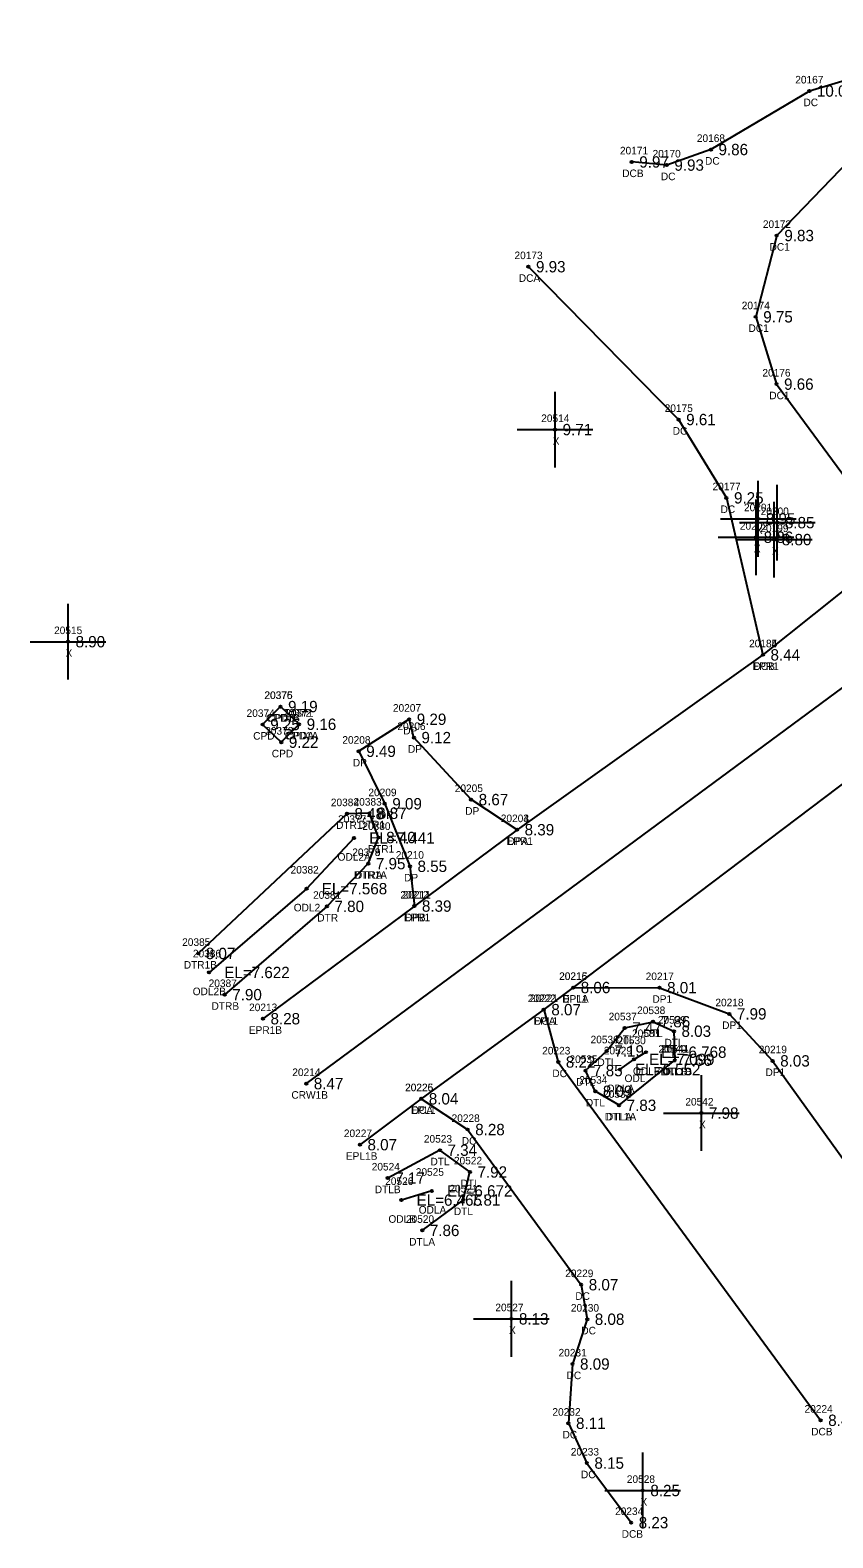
# Model space of a CAD drawing. Extents: x 2608745 to 2610333, y 641917 to 643463.
# Drawn here: x 2608854.6 to 2608960.7, y 642940.8 to 643140 of the extents above; entities that cross this region are included whole.
import ezdxf

# ---------------------------------------------------------------- set-up
doc = ezdxf.new("R2010")
doc.units = 0
for name, color, linetype in [('RD_DTM_BkLn1', 7, 'Continuous'), ('RD_EX_Conc', 7, 'Continuous'), ('RD_EX_Conc_txCode', 7, 'Continuous'), ('RD_EX_Driveway', 7, 'Continuous'), ('RD_EX_Driveway_txCode', 7, 'Continuous'), ('RD_EX_H2O', 7, 'Continuous'), ('RD_EX_H2O_txCode', 7, 'Continuous'), ('RD_EX_Misc', 7, 'Continuous'), ('RD_EX_Misc_txCode', 7, 'Continuous'), ('RD_EX_Road', 7, 'Continuous'), ('RD_EX_Road_txCode', 7, 'Continuous'), ('RD_EX_TX_Conc_ELEV', 7, 'Continuous'), ('RD_EX_TX_Driveway_ELEV', 7, 'Continuous'), ('RD_EX_TX_H2O_ELEV', 7, 'Continuous'), ('RD_EX_TX_Misc_ELEV', 7, 'Continuous'), ('RD_EX_TX_Road_ELEV', 7, 'Continuous'), ('RD_HC_Survey_ELEV', 7, 'Continuous'), ('RD_HC_Survey_txCode', 7, 'Continuous'), ('RD_SMD_Locator', 7, 'Continuous')]:
    doc.layers.add(name, color=color, linetype=linetype)

msp = doc.modelspace()

# ---------------------------------------------------------------- linework, layer by layer
at = {"layer": 'RD_DTM_BkLn1'}
msp.add_lwpolyline([(2609056.24, 643122.81), (2608974.26, 643062.19), (2608891.12, 643000.79)], dxfattribs=at)
at = {"layer": 'RD_EX_Conc'}
msp.add_line((2608890.18, 643048.26), (2608887.72, 643050.6), dxfattribs=at)
for points in [[(2609024.85, 643112.94), (2609016.08, 643116.29), (2609004.89, 643123.89), (2608993.8, 643132.32), (2608984.26, 643135.98), (2608977.64, 643134.66), (2608968.2, 643135.07), (2608957.58, 643131.92), (2608944.58, 643124.19), (2608938.75, 643122.14), (2608934.12, 643122.55)], [(2609007.07, 643099.58), (2609002.03, 643107.42), (2608993.62, 643115.7), (2608984.79, 643122.12), (2608974.31, 643125.61), (2608962.85, 643122.75), (2608953.28, 643112.83), (2608950.49, 643102.09), (2608953.24, 643093.2), (2608962.51, 643080.66), (2608966.87, 643076.38), (2608971.66, 643073.57)], [(2608920.47, 643108.71), (2608940.31, 643088.52), (2608946.63, 643078.17), (2608951.45, 643057.43)], [(2608890.18, 643048.26), (2608887.82, 643045.89), (2608885.36, 643048.23), (2608887.72, 643050.6)], [(2608922.5, 643010.56), (2608924.41, 643003.64), (2608959.07, 642956.31)], [(2608906.31, 642998.78), (2608912.44, 642994.72), (2608927.44, 642974.22), (2608928.24, 642969.66), (2608926.29, 642963.74), (2608925.76, 642955.91), (2608928.19, 642950.65), (2608934.04, 642942.79)]]:
    msp.add_lwpolyline(points, dxfattribs=at)
at = {"layer": 'RD_EX_Driveway'}
for points in [[(2608918.97, 643034.33), (2608912.9, 643038.31), (2608905.34, 643046.5), (2608904.72, 643048.92), (2608898.05, 643044.69), (2608901.49, 643037.76), (2608904.82, 643029.5), (2608905.4, 643024.24)], [(2608926.38, 643013.48), (2608937.79, 643013.46), (2608947.01, 643010), (2608952.73, 643003.79), (2608980.52, 642965.19)]]:
    msp.add_lwpolyline(points, dxfattribs=at)
at = {"layer": 'RD_EX_H2O'}
for p, q in [((2608932.45, 642997.92), (2608939.81, 643003.88)), ((2608907.71, 642986.61), (2608903.69, 642985.4))]:
    msp.add_line(p, q, dxfattribs=at)
for points in [[(2608899.32, 643029.85), (2608900.68, 643033.3), (2608899.48, 643036.51), (2608896.49, 643036.44), (2608876.85, 643017.98)], [(2608897.44, 643033.24), (2608891.17, 643026.54), (2608878.29, 643015.47)], [(2608899.32, 643029.85), (2608893.85, 643024.2), (2608880.35, 643012.54)], [(2608932.45, 642997.92), (2608929.3, 642999.77), (2608928.01, 643002.51), (2608930.82, 643005.11), (2608933.19, 643008.15), (2608936.94, 643008.97), (2608939.69, 643007.71), (2608939.81, 643003.88)], [(2608932.55, 643002.65), (2608934.41, 643003.99), (2608935.99, 643004.94)], [(2608906.45, 642981.39), (2608911.86, 642985.41), (2608912.75, 642989.11), (2608908.78, 642991.99), (2608901.89, 642988.31)]]:
    msp.add_lwpolyline(points, dxfattribs=at)
at = {"layer": 'RD_EX_Misc'}
for p, q in [((2608923.99, 643082.19), (2608923.99, 643092.19)), ((2608918.99, 643087.19), (2608928.99, 643087.19)), ((2608950.83, 643070.4), (2608950.83, 643080.4)), ((2608953.35, 643069.9), (2608953.35, 643079.9)), ((2608950.55, 643067.97), (2608950.55, 643077.97)), ((2608952.95, 643067.66), (2608952.95, 643077.66)), ((2608945.83, 643075.4), (2608955.83, 643075.4)), ((2608948.35, 643074.9), (2608958.35, 643074.9)), ((2608945.55, 643072.97), (2608955.55, 643072.97)), ((2608947.95, 643072.66), (2608957.95, 643072.66)), ((2608859.65, 643054.17), (2608859.65, 643064.17)), ((2608854.65, 643059.17), (2608864.65, 643059.17)), ((2608943.32, 642991.89), (2608943.32, 643001.89)), ((2608938.32, 642996.89), (2608948.32, 642996.89)), ((2608918.22, 642964.71), (2608918.22, 642974.71)), ((2608913.22, 642969.71), (2608923.22, 642969.71)), ((2608935.58, 642942.03), (2608935.58, 642952.03)), ((2608930.58, 642947.03), (2608940.58, 642947.03))]:
    msp.add_line(p, q, dxfattribs=at)
at = {"layer": 'RD_EX_Road'}
for points in [[(2609039.6, 643139.96), (2609040.08, 643133.73), (2609039.13, 643128.33), (2609035.72, 643122.79), (2609029.12, 643116.23), (2609024.85, 643112.94), (2609007.07, 643099.58), (2608971.66, 643073.57), (2608951.45, 643057.43), (2608918.97, 643034.33), (2608905.4, 643024.24), (2608885.4, 643009.36)], [(2609073.88, 643106.95), (2609065.56, 643108.46), (2609056.72, 643107.24), (2609047.16, 643103.56), (2608981.11, 643054.04), (2608966.97, 643044.2), (2608926.38, 643013.48), (2608922.5, 643010.56), (2608906.31, 642998.78), (2608898.21, 642992.72)]]:
    msp.add_lwpolyline(points, dxfattribs=at)
at = {"layer": 'RD_SMD_Locator'}
for centre in [(2608957.58, 643131.92), (2608934.12, 643122.55), (2608944.58, 643124.19), (2608938.75, 643122.14), (2608953.28, 643112.83), (2608920.47, 643108.71), (2608950.49, 643102.09), (2608953.24, 643093.2), (2608940.31, 643088.52), (2608923.99, 643087.19), (2608946.63, 643078.17), (2608950.83, 643075.4), (2608953.35, 643074.9), (2608950.55, 643072.97), (2608952.95, 643072.66), (2608859.65, 643059.17), (2608951.45, 643057.43), (2608951.45, 643057.43), (2608887.72, 643050.6), (2608887.72, 643050.6), (2608904.72, 643048.92), (2608885.36, 643048.23), (2608890.18, 643048.26), (2608890.18, 643048.26), (2608887.82, 643045.89), (2608898.05, 643044.69), (2608905.34, 643046.5), (2608901.49, 643037.76), (2608912.9, 643038.31), (2608896.49, 643036.44), (2608899.48, 643036.51), (2608897.44, 643033.24), (2608900.68, 643033.3), (2608918.97, 643034.33), (2608918.97, 643034.33), (2608899.32, 643029.85), (2608899.32, 643029.85), (2608904.82, 643029.5), (2608891.17, 643026.54), (2608893.85, 643024.2), (2608905.4, 643024.24), (2608905.4, 643024.24), (2608876.85, 643017.98), (2608878.29, 643015.47), (2608926.38, 643013.48), (2608926.38, 643013.48), (2608937.79, 643013.46), (2608880.35, 643012.54), (2608885.4, 643009.36), (2608922.5, 643010.56), (2608922.5, 643010.56), (2608936.94, 643008.97), (2608947.01, 643010), (2608933.19, 643008.15), (2608939.69, 643007.71), (2608930.82, 643005.11), (2608935.99, 643004.94), (2608924.41, 643003.64), (2608934.41, 643003.99), (2608939.81, 643003.88), (2608939.81, 643003.88), (2608952.73, 643003.79), (2608891.12, 643000.79), (2608928.01, 643002.51), (2608932.55, 643002.65), (2608906.31, 642998.78), (2608906.31, 642998.78), (2608929.3, 642999.77), (2608932.45, 642997.92), (2608932.45, 642997.92), (2608943.32, 642996.89), (2608912.44, 642994.72), (2608898.21, 642992.72), (2608908.78, 642991.99), (2608912.75, 642989.11), (2608901.89, 642988.31), (2608903.69, 642985.4), (2608907.71, 642986.61), (2608911.86, 642985.41), (2608906.45, 642981.39), (2608927.44, 642974.22), (2608918.22, 642969.71), (2608928.24, 642969.66), (2608926.29, 642963.74), (2608925.76, 642955.91), (2608959.07, 642956.31), (2608928.19, 642950.65), (2608935.58, 642947.03), (2608934.04, 642942.79)]:
    msp.add_circle(centre, 0.15, dxfattribs=at)

# ---------------------------------------------------------------- texts
at = {"layer": 'RD_EX_Conc_txCode'}
for s, p in [('20167', (2608955.72, 643132.92)), ('DC', (2608956.8, 643129.92)), ('20171', (2608932.56, 643123.55)), ('20168', (2608942.72, 643125.19)), ('20170', (2608936.87, 643123.14)), ('DC', (2608943.8, 643122.19)), ('DCB', (2608932.86, 643120.55)), ('DC', (2608937.97, 643120.14)), ('20172', (2608951.44, 643113.83)), ('20173', (2608918.63, 643109.71)), ('DC1', (2608952.33, 643110.83)), ('DCA', (2608919.2, 643106.71)), ('20174', (2608948.65, 643103.09)), ('DC1', (2608949.54, 643100.09)), ('20176', (2608951.38, 643094.2)), ('20175', (2608938.47, 643089.52)), ('DC1', (2608952.29, 643091.2)), ('DC', (2608939.53, 643086.52)), ('20177', (2608944.79, 643079.17)), ('DC', (2608945.85, 643076.17)), ('20184', (2608949.62, 643058.43)), ('DCB', (2608950.2, 643055.43)), ('20376', (2608885.58, 643051.6)), ('20375', (2608885.61, 643051.6)), ('20374', (2608883.24, 643049.23)), ('CPD1B', (2608885.83, 643048.6)), ('CPDB', (2608886, 643048.6)), ('20372', (2608888.06, 643049.26)), ('20371', (2608888.34, 643049.26)), ('CPD', (2608884.11, 643046.23)), ('20373', (2608885.7, 643046.89)), ('CPD1A', (2608888.27, 643046.26)), ('CPDA', (2608888.44, 643046.26)), ('CPD', (2608886.57, 643043.89)), ('20222', (2608920.38, 643011.56)), ('DCA', (2608921.23, 643008.56)), ('20223', (2608922.29, 643004.64)), ('DC', (2608923.63, 643001.64)), ('20226', (2608904.17, 642999.78)), ('DCA', (2608905.04, 642996.78)), ('20228', (2608910.32, 642995.72)), ('DC', (2608911.66, 642992.72)), ('20229', (2608925.33, 642975.22)), ('DC', (2608926.67, 642972.22)), ('20230', (2608926.08, 642970.66)), ('DC', (2608927.46, 642967.66)), ('20231', (2608924.45, 642964.74)), ('DC', (2608925.51, 642961.74)), ('20232', (2608923.64, 642956.91)), ('20224', (2608956.95, 642957.31)), ('DCB', (2608957.82, 642954.31)), ('DC', (2608924.98, 642953.91)), ('20233', (2608926.07, 642951.65)), ('DC', (2608927.41, 642948.65)), ('20234', (2608931.92, 642943.79)), ('DCB', (2608932.79, 642940.79))]:
    msp.add_text(s, height=1, dxfattribs=at).set_placement(p)
at = {"layer": 'RD_EX_Driveway_txCode'}
for s, p in [('20207', (2608902.57, 643049.92)), ('20208', (2608895.89, 643045.69)), ('20206', (2608903.16, 643047.5)), ('DP', (2608903.94, 643046.92)), ('DP', (2608904.56, 643044.5)), ('DP', (2608897.27, 643042.69)), ('20209', (2608899.33, 643038.76)), ('20205', (2608910.74, 643039.31)), ('DP', (2608900.71, 643035.76)), ('DP', (2608912.12, 643036.31)), ('20204', (2608916.82, 643035.33)), ('DPA', (2608917.7, 643032.33)), ('20210', (2608902.95, 643030.5)), ('DP', (2608904.04, 643027.5)), ('20211', (2608903.85, 643025.24)), ('DPB', (2608904.15, 643022.24)), ('20216', (2608924.52, 643014.48)), ('20217', (2608935.96, 643014.46)), ('DP1A', (2608924.94, 643011.48)), ('DP1', (2608936.85, 643011.46)), ('20218', (2608945.17, 643011)), ('DP1', (2608946.06, 643008)), ('20219', (2608950.9, 643004.79)), ('DP1', (2608951.79, 643001.79))]:
    msp.add_text(s, height=1, dxfattribs=at).set_placement(p)
at = {"layer": 'RD_EX_H2O_txCode'}
for s, p in [('20384', (2608894.37, 643037.44)), ('20383', (2608897.37, 643037.51)), ('DTR1', (2608895.06, 643034.44)), ('20377', (2608895.33, 643035.24)), ('DTR1', (2608898.05, 643034.51)), ('20380', (2608898.53, 643034.3)), ('ODL2A', (2608895.26, 643030.24)), ('20378', (2608897.2, 643030.85)), ('20379', (2608897.2, 643030.85)), ('DTR1', (2608899.25, 643031.3)), ('20382', (2608889.05, 643028.54)), ('DTR1A', (2608897.4, 643027.85)), ('DTRA', (2608897.56, 643027.85)), ('20381', (2608892.02, 643025.2)), ('ODL2', (2608889.47, 643023.54)), ('DTR', (2608892.58, 643022.2)), ('20385', (2608874.73, 643018.98)), ('DTR1B', (2608874.94, 643015.98)), ('20386', (2608876.15, 643017.47)), ('ODL2B', (2608876.12, 643012.47)), ('20387', (2608878.23, 643013.54)), ('DTRB', (2608878.61, 643010.54)), ('20538', (2608934.83, 643009.97)), ('20537', (2608931.07, 643009.15)), ('20539', (2608937.57, 643008.71)), ('20536', (2608928.68, 643006.11)), ('DTL', (2608931.95, 643006.15)), ('20530', (2608932.25, 643005.99)), ('20531', (2608934.16, 643006.94)), ('DTL', (2608935.7, 643006.97)), ('20529', (2608930.43, 643004.65)), ('20540', (2608937.65, 643004.88)), ('20541', (2608937.97, 643004.88)), ('DTL', (2608938.44, 643005.71)), ('20535', (2608925.89, 643003.51)), ('DTL', (2608929.58, 643003.11)), ('ODLB', (2608934.28, 643001.94)), ('DTL1B', (2608937.93, 643001.88)), ('DTLB', (2608938.09, 643001.88)), ('DTL', (2608926.77, 643000.51)), ('20534', (2608927.19, 643000.77)), ('ODL', (2608933.17, 643000.99)), ('20532', (2608930.33, 642998.92)), ('20533', (2608930.33, 642998.92)), ('ODLA', (2608930.81, 642999.65)), ('DTL', (2608928.06, 642997.77)), ('DTL1A', (2608930.55, 642995.92)), ('DTLA', (2608930.72, 642995.92)), ('20523', (2608906.66, 642992.99)), ('DTL', (2608907.53, 642989.99)), ('20522', (2608910.63, 642990.11)), ('20524', (2608899.77, 642989.31)), ('20525', (2608905.59, 642988.61)), ('DTLB', (2608900.17, 642986.31)), ('20526', (2608901.55, 642987.4)), ('20521', (2608910.03, 642986.41)), ('DTL', (2608911.5, 642987.11)), ('ODLB', (2608901.98, 642982.4)), ('20520', (2608904.29, 642982.39)), ('ODLA', (2608905.98, 642983.61)), ('DTL', (2608910.62, 642983.41)), ('DTLA', (2608904.72, 642979.39))]:
    msp.add_text(s, height=1, dxfattribs=at).set_placement(p)
at = {"layer": 'RD_EX_Misc_txCode'}
for s, p in [('20514', (2608922.16, 643088.19)), ('X', (2608923.68, 643085.19)), ('20201', (2608948.95, 643076.4)), ('20200', (2608951.15, 643075.9)), ('20202', (2608948.4, 643073.97)), ('20199', (2608951.11, 643073.66)), ('X', (2608950.51, 643073.4)), ('X', (2608953.03, 643072.9)), ('X', (2608950.24, 643070.97)), ('X', (2608952.63, 643070.66)), ('20515', (2608857.81, 643060.17)), ('X', (2608859.33, 643057.17)), ('20542', (2608941.2, 642997.89)), ('X', (2608943, 642994.89)), ('20527', (2608916.1, 642970.71)), ('X', (2608917.91, 642967.71)), ('20528', (2608933.47, 642948.03)), ('X', (2608935.27, 642945.03))]:
    msp.add_text(s, height=1, dxfattribs=at).set_placement(p)
at = {"layer": 'RD_EX_Road_txCode'}
for s, p in [('20185', (2608949.62, 643058.43)), ('EPR1', (2608950.06, 643055.43)), ('20203', (2608916.82, 643035.33)), ('EPR1', (2608917.58, 643032.33)), ('20212', (2608903.56, 643025.24)), ('EPR1', (2608904, 643022.24)), ('20215', (2608924.54, 643014.48)), ('20213', (2608883.57, 643010.36)), ('20221', (2608920.66, 643011.56)), ('EPL1', (2608925.01, 643011.48)), ('EPL1', (2608921.13, 643008.56)), ('EPR1B', (2608883.54, 643007.36)), ('20225', (2608904.19, 642999.78)), ('EPL1', (2608904.94, 642996.78)), ('20227', (2608896.09, 642993.72)), ('EPL1B', (2608896.36, 642990.72))]:
    msp.add_text(s, height=1, dxfattribs=at).set_placement(p)
at = {"layer": 'RD_EX_TX_Conc_ELEV'}
for s, p in [('10.06', (2608958.58, 643131.17)), ('9.86', (2608945.58, 643123.44)), ('9.97', (2608935.12, 643121.8)), ('9.93', (2608939.75, 643121.39)), ('9.83', (2608954.28, 643112.08)), ('9.93', (2608921.47, 643107.96)), ('9.75', (2608951.49, 643101.34)), ('9.66', (2608954.24, 643092.45)), ('9.61', (2608941.31, 643087.77)), ('9.25', (2608947.63, 643077.42)), ('8.44', (2608952.45, 643056.68)), ('9.19', (2608888.72, 643049.85)), ('9.19', (2608888.72, 643049.85)), ('9.25', (2608886.36, 643047.48)), ('9.16', (2608891.18, 643047.51)), ('9.16', (2608891.18, 643047.51)), ('9.22', (2608888.82, 643045.14)), ('8.07', (2608923.5, 643009.81)), ('8.22', (2608925.41, 643002.89)), ('8.04', (2608907.31, 642998.03)), ('8.28', (2608913.44, 642993.97)), ('8.07', (2608928.44, 642973.47)), ('8.08', (2608929.24, 642968.91)), ('8.09', (2608927.29, 642962.99)), ('8.47', (2608960.07, 642955.56)), ('8.11', (2608926.76, 642955.16)), ('8.15', (2608929.19, 642949.9)), ('8.23', (2608935.04, 642942.04))]:
    msp.add_text(s, height=1.5, dxfattribs=at).set_placement(p)
at = {"layer": 'RD_EX_TX_Driveway_ELEV'}
for s, p in [('9.29', (2608905.72, 643048.17)), ('9.12', (2608906.34, 643045.75)), ('9.49', (2608899.05, 643043.94)), ('8.67', (2608913.9, 643037.56)), ('9.09', (2608902.49, 643037.01)), ('8.39', (2608919.97, 643033.58)), ('8.55', (2608905.82, 643028.75)), ('8.39', (2608906.4, 643023.49)), ('8.06', (2608927.38, 643012.73)), ('8.01', (2608938.79, 643012.71)), ('7.99', (2608948.01, 643009.25)), ('8.03', (2608953.73, 643003.04))]:
    msp.add_text(s, height=1.5, dxfattribs=at).set_placement(p)
at = {"layer": 'RD_EX_TX_H2O_ELEV'}
for s, p in [('8.48', (2608897.49, 643035.69)), ('8.87', (2608900.48, 643035.76)), ('EL=7.441', (2608899.44, 643032.49)), ('8.40', (2608901.68, 643032.55)), ('7.95', (2608900.32, 643029.1)), ('7.95', (2608900.32, 643029.1)), ('EL=7.568', (2608893.17, 643025.79)), ('7.80', (2608894.85, 643023.45)), ('8.07', (2608877.85, 643017.23)), ('EL=7.622', (2608880.29, 643014.72)), ('7.90', (2608881.35, 643011.79)), ('7.47', (2608934.19, 643007.4)), ('7.86', (2608937.94, 643008.22)), ('8.03', (2608940.69, 643006.96)), ('7.19', (2608931.82, 643004.36)), ('EL=6.768', (2608937.99, 643004.19)), ('7.85', (2608929.01, 643001.76)), ('EL=6.552', (2608934.55, 643001.9)), ('EL=7.099', (2608936.41, 643003.24)), ('7.66', (2608940.81, 643003.13)), ('7.66', (2608940.81, 643003.13)), ('8.09', (2608930.3, 642999.02)), ('7.83', (2608933.45, 642997.17)), ('7.83', (2608933.45, 642997.17)), ('7.34', (2608909.78, 642991.24)), ('7.17', (2608902.89, 642987.56)), ('7.92', (2608913.75, 642988.36)), ('EL=6.672', (2608909.71, 642985.86)), ('EL=6.465', (2608905.69, 642984.65)), ('7.81', (2608912.86, 642984.66)), ('7.86', (2608907.45, 642980.64))]:
    msp.add_text(s, height=1.5, dxfattribs=at).set_placement(p)
at = {"layer": 'RD_EX_TX_Misc_ELEV'}
for s, p in [('9.71', (2608924.99, 643086.44)), ('8.95', (2608951.83, 643074.65)), ('8.85', (2608954.35, 643074.15)), ('8.86', (2608951.55, 643072.22)), ('8.80', (2608953.95, 643071.91)), ('8.90', (2608860.65, 643058.42)), ('7.98', (2608944.32, 642996.14)), ('8.13', (2608919.22, 642968.96)), ('8.25', (2608936.58, 642946.28))]:
    msp.add_text(s, height=1.5, dxfattribs=at).set_placement(p)
at = {"layer": 'RD_EX_TX_Road_ELEV'}
for s, p in [('8.44', (2608952.45, 643056.68)), ('8.39', (2608919.97, 643033.58)), ('8.39', (2608906.4, 643023.49)), ('8.06', (2608927.38, 643012.73)), ('8.07', (2608923.5, 643009.81)), ('8.28', (2608886.4, 643008.61)), ('8.04', (2608907.31, 642998.03)), ('8.07', (2608899.21, 642991.97))]:
    msp.add_text(s, height=1.5, dxfattribs=at).set_placement(p)
at = {"layer": 'RD_HC_Survey_ELEV'}
msp.add_text('8.47', height=1.5, dxfattribs=at).set_placement((2608892.12, 643000.04))
at = {"layer": 'RD_HC_Survey_txCode'}
for s, p in [('20214', (2608889.28, 643001.79)), ('CRW1B', (2608889.16, 642998.79))]:
    msp.add_text(s, height=1, dxfattribs=at).set_placement(p)

doc.saveas('drawing.dxf')
